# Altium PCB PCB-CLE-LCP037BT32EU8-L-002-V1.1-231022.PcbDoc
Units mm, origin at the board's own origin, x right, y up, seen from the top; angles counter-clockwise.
Board outline 48.21 x 48.21 mm, 2 copper layers (Top Layer, Bottom Layer), stack 1.571 mm thick; 83 components, 45 nets, 245 pads, 56 vias.
Unrouted connection lines stored in the file: 1.
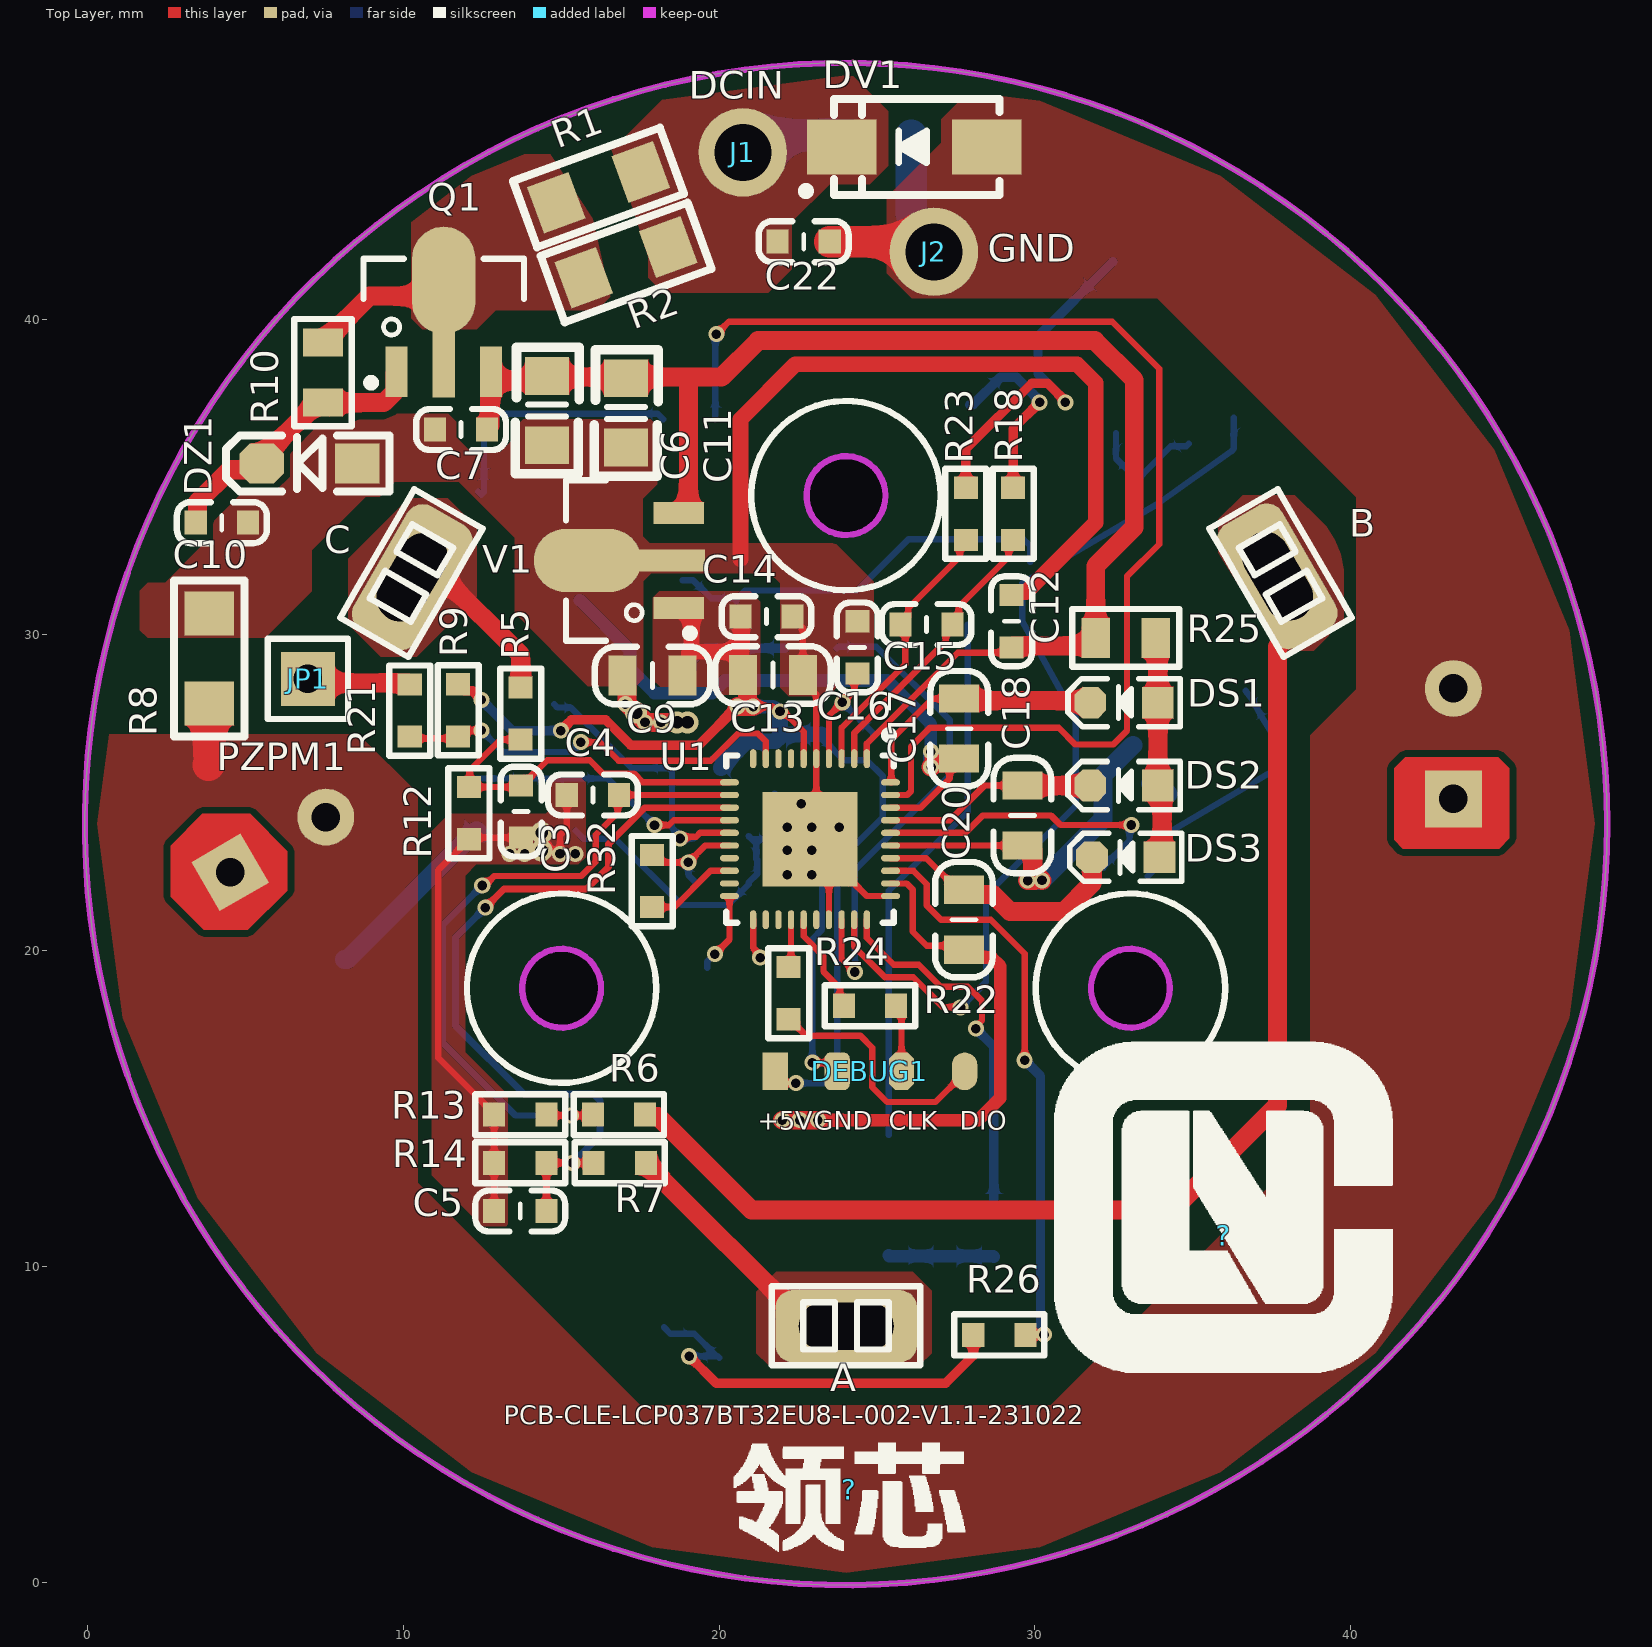
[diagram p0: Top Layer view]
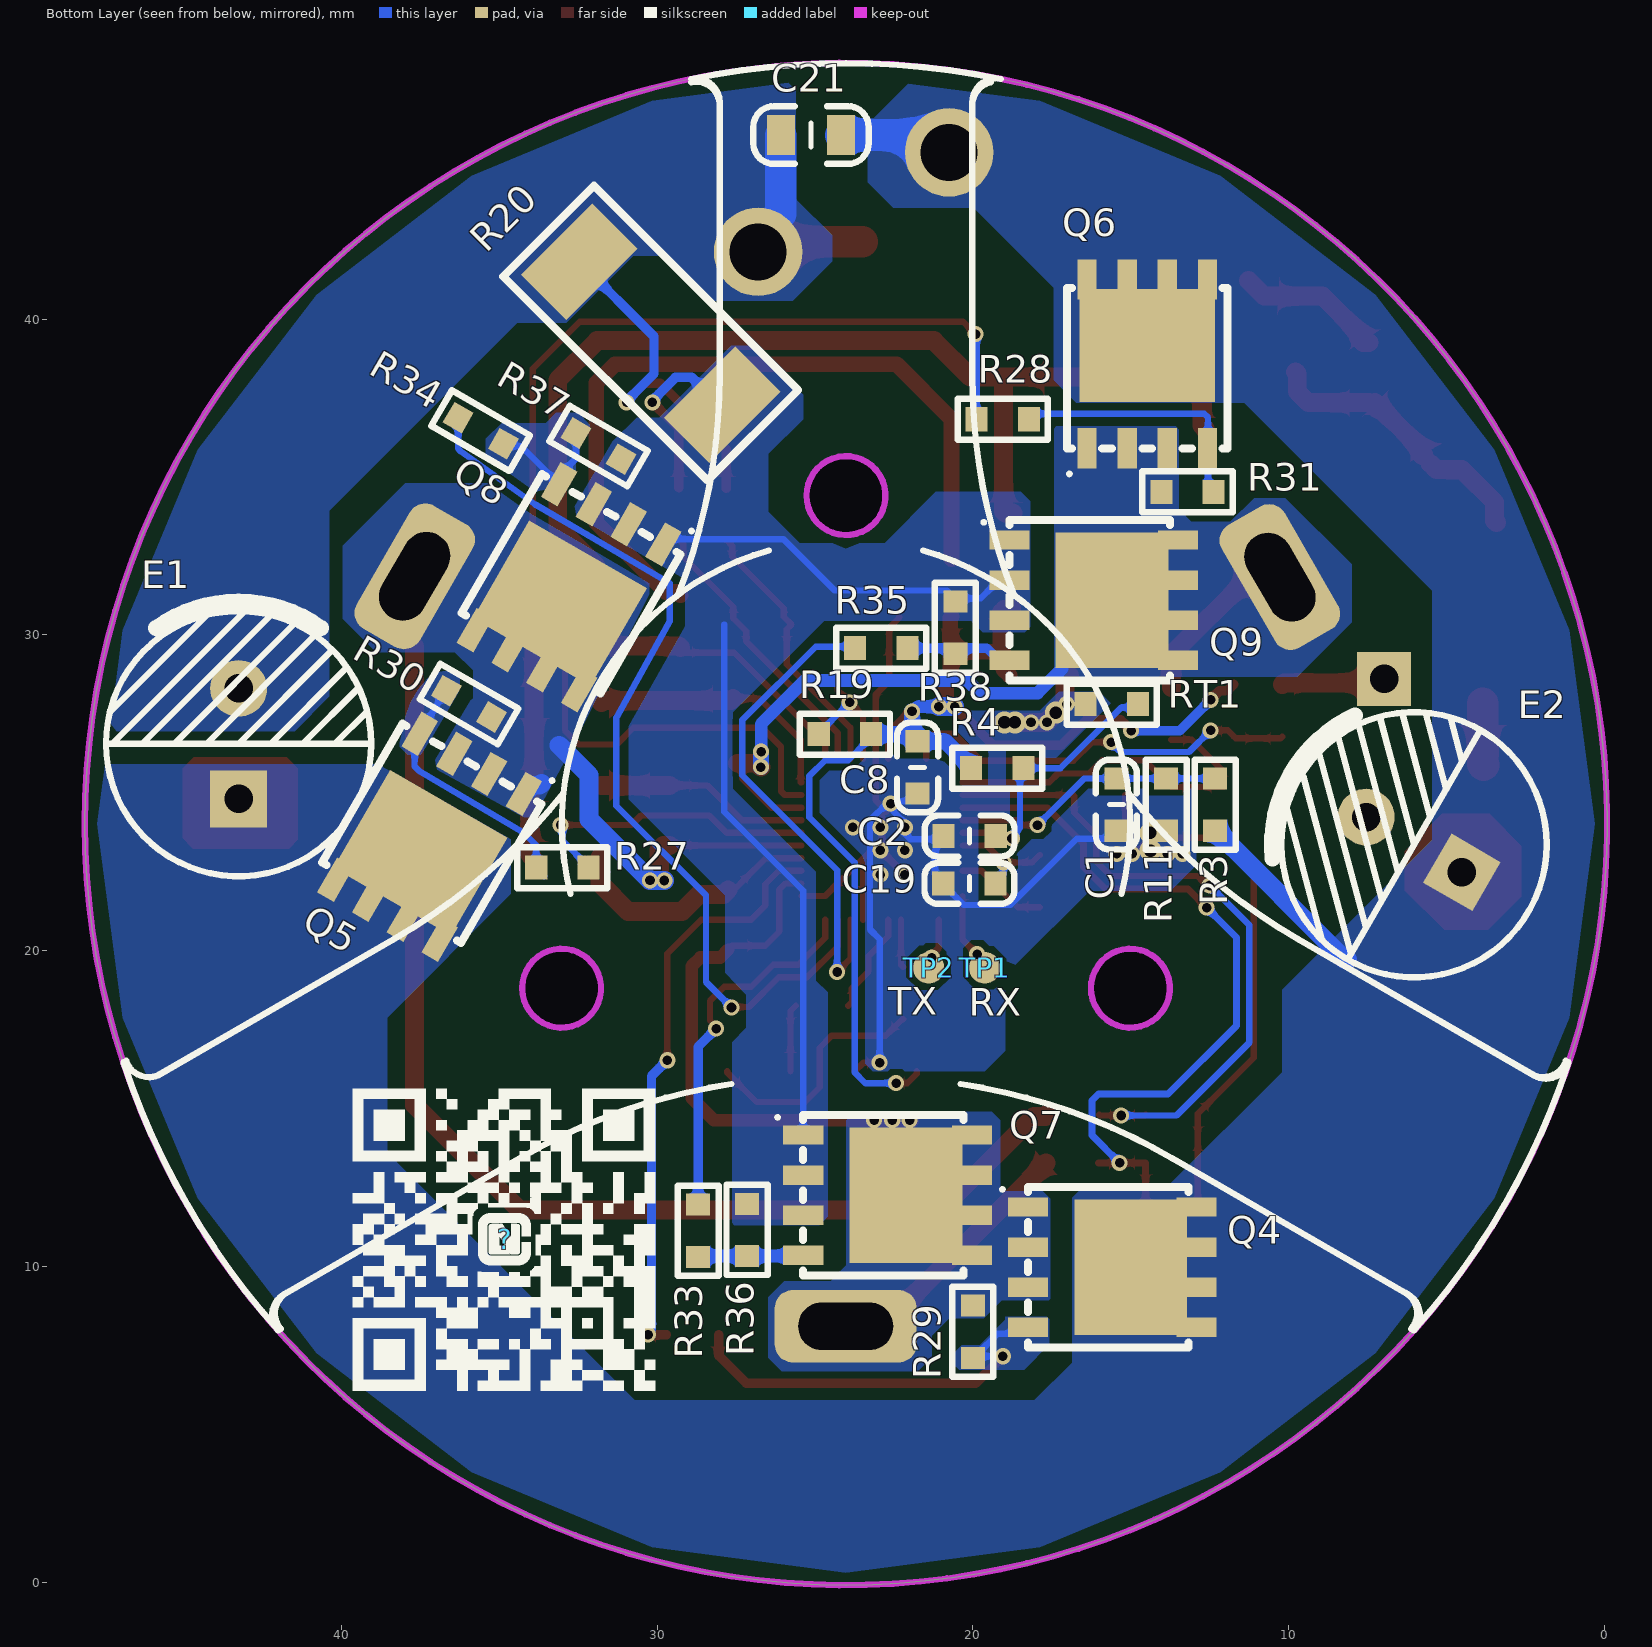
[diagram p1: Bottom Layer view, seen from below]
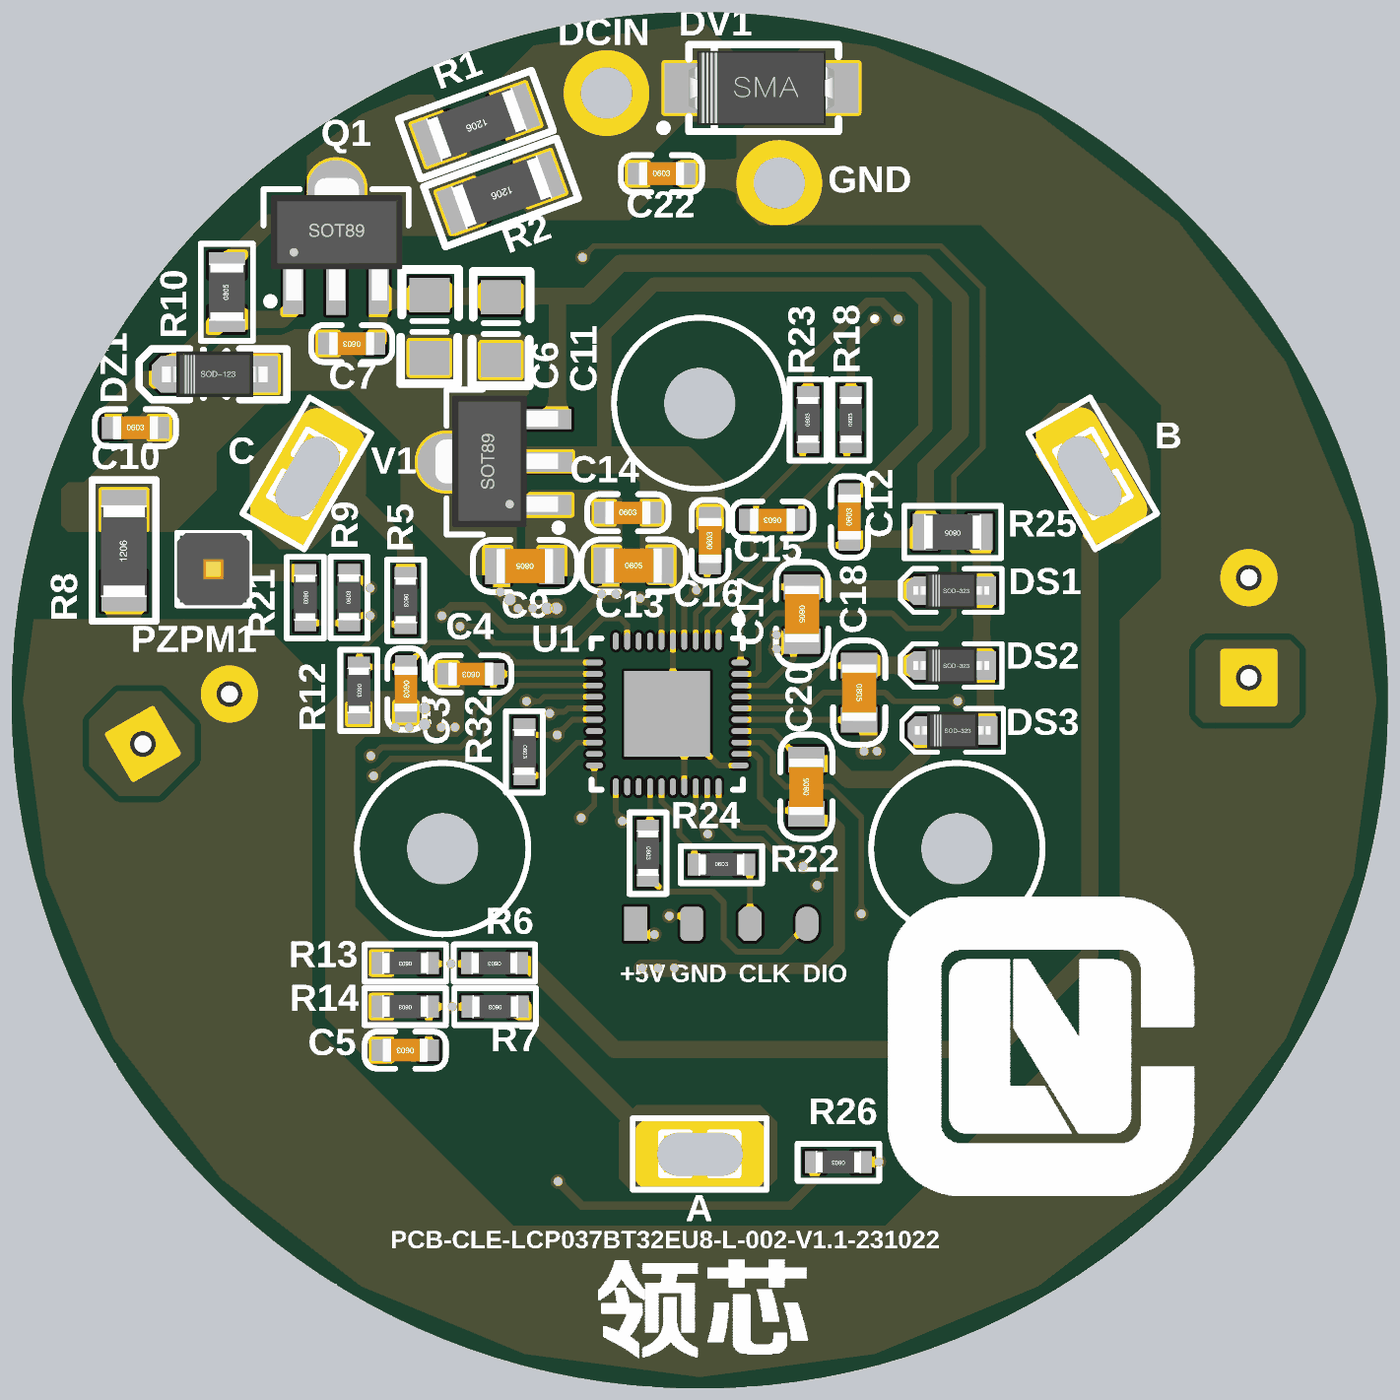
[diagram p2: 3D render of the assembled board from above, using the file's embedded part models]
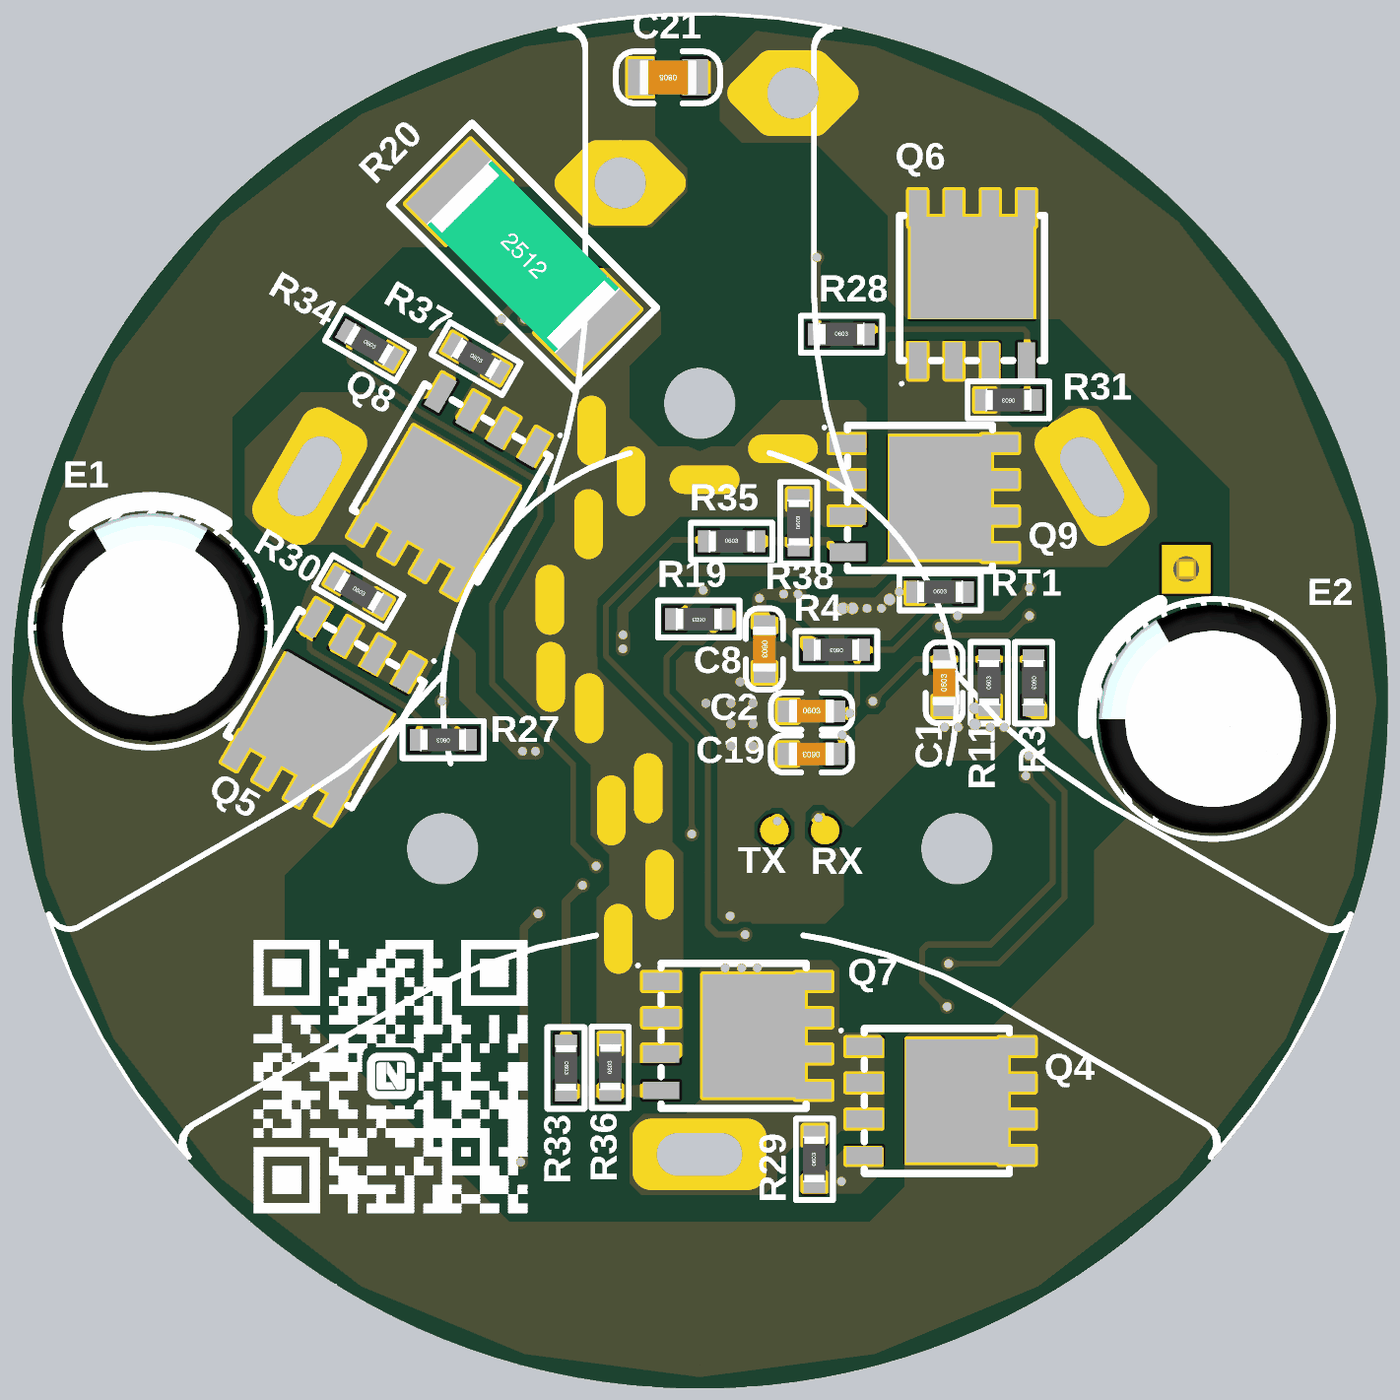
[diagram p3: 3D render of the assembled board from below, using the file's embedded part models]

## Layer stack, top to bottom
Top Solder: solder mask 0.0102, Solder Resist, Dk 3.5
Top Layer: signal copper 0.0356
Dielectric1: dielectric 1.5, FR-4, Dk 4.8
Bottom Layer: signal copper 0.0356
Bottom Solder: solder mask 0.0102, Solder Resist, Dk 3.5

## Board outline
-0.087,24.01 ccw(c24.018,24.01) 24.018,-0.095 ccw(c24.018,24.01) 48.123,24.01 ccw(c24.018,24.01) 24.018,48.114 ccw(c24.018,24.01)
cut-out: 22.768,34.41 ccw(c24.018,34.41) 24.018,33.16 ccw(c24.018,34.41) 25.268,34.41 ccw(c24.018,34.41) 24.018,35.66 ccw(c24.018,34.41)
cut-out: 13.762,18.81 ccw(c15.012,18.81) 15.012,17.56 ccw(c15.012,18.81) 16.262,18.81 ccw(c15.012,18.81) 15.012,20.06 ccw(c15.012,18.81)
cut-out: 31.775,18.81 ccw(c33.025,18.81) 33.025,17.56 ccw(c33.025,18.81) 34.275,18.81 ccw(c33.025,18.81) 33.025,20.06 ccw(c33.025,18.81)

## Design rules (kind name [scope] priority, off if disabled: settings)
Clearance [All] p1: gap=0.2 ignorepadtopadclearanceinfootprint=FALSE
ComponentClearance [All] p1: gap=0 collisioncheckmode=3 verticalgap=0 showdistances=FALSE
FabricationTestpoint [(IsPad And (OnTopLayer Or OnBottomLayer))] p1: side=3 testpointundercomponent=TRUE minsize=1.016 maxsize=2.54 preferedsize=1.524 minholesize=0 maxholesize=1.016 preferedholesize=0.813 testpointgrid=0.025 allowsidetop=TRUE allowsidebottom=TRUE usegrid=TRUE gridtolerance=0
Height [All] p1: minheight=0 maxheight=254 prefheight=12.7
HoleSize [All] p1: absolutevalues=TRUE maxlimit=25.4 minlimit=0.025 maxpercent=80.000 minpercent=20.000
HoleToHoleClearance [All] p1: gap=0 allowstackedmicrovias=TRUE
MinimumSolderMaskSliver [All] p1: minsoldermaskwidth=0
PlaneConnect [All] p1: planeconnectstyle=Direct reliefexpansion=0.508 reliefentries=4 reliefconductorwidth=0.254 reliefairgap=0.254
PolygonConnect [IsVia] p1: connectstyle=Direct reliefconductorwidth=0.254 reliefentries=4 polygonreliefangle="90 Angle" airgapwidth=0.254
PolygonConnect PolygonConnect_1 [All] p2: connectstyle=Direct reliefconductorwidth=0.254 reliefentries=4 polygonreliefangle="90 Angle" airgapwidth=0.254
RoutingVias [All] p1: holewidth=0.305 width=0.508 viastyle="Through Hole" minholewidth=0.025 minwidth=0.025 maxholewidth=0.711 maxwidth=1.27
SilkToSilkClearance [All] p1: silktosilkclearance=0
SilkToSolderMaskClearance SilkscreenOverComponentPads [IsPad] p1: minsilkscreentomaskgap=0 clearancetoexposedcopper=TRUE
SolderMaskExpansion [All] p1: expansion=0.102 istentingtop=FALSE
Width [All] p1: maxlimit=25.4 minlimit=0.025 preferedwidth=0.254
21 further rules are at their usual default settings.

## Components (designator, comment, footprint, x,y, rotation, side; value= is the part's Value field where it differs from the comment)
? "LOGO-MA" LOGO-MA 34.803,10.853 r180 bottom
? "LOGO-TU" LOGO-TU 35.977,10.972 r0 top
? "LOGO-ZI" LOGO-ZI 24.128,2.928 r0 top
C1 "104/50V" C0603 15.455,24.623 r90 bottom
C2 "103/50V" C0603 20.103,23.628 r180 bottom
C3 "102/50V" C0603 13.728,24.403 r270 top
C4 "102/50V" C0603 16.003,24.928 r180 top
C5 "102/50V" C0603 13.703,11.753 r180 top
C6 "106/50V" C0805#1 14.553,37.103 r270 top
C7 "104/50V" C0603 11.828,36.503 r180 top
C8 "104/50V" C0603 21.753,25.803 r270 bottom
C9 "106/50V" C0805#2 17.893,28.713 r180 top
C10 "104/50V" C0603 4.251,33.553 r0 top
C11 "106/50V" C0805#1 17.053,37.028 r270 top
C12 "104/50V" C0603 29.261,30.429 r90 top
C13 "106/50V" C0805#2 21.703,28.728 r0 top
C14 "104/50V" C0603 21.501,30.578 r0 top
C15 "101/50V" C0603 26.568,30.328 r180 top
C16 "104/50V" C0603 24.378,29.603 r90 top
C17 "106/25V" C0805#2 27.603,27.028 r270 top
C18 "106/25V" C0805#2 29.603,24.278 r270 top
C19 "105/50V" C0603 20.111,22.128 r0 bottom
C20 "106/25V" C0805#2 27.753,20.978 r90 top
C21 "106/50V" C0805#2 25.128,45.828 r0 bottom
C22 "104/50V" C0603 22.678,42.453 r0 top
DEBUG1 "PZ4-SHAOLU" DEBUG2.00 21.778,16.178 r0 top
DS1 "1N4148" SOD-323 32.828,27.853 r180 top
DS2 "1N4148" SOD-323 32.828,25.228 r180 top
DS3 "1N4148" SOD-323 32.878,22.953 r180 top
DV1 "SMA18V" SMA 26.178,45.453 r180 top
DZ1 "BZT52C12" SOD-123 7.028,35.428 r180 top
E1 "470uf/35V" CE-3.5-8-11 43.253,26.553 r90 bottom
E2 "470uf/35V" CE-3.5-8-11 6.028,23.353 r30 bottom
J1 "DCIN" HOLD-16AWG_RED 20.753,45.278 r180 top
J2 "GND" HOLD-16AWG_BLK 26.803,42.128 r0 top
JP1 "PZPM1" PZ2.54-D-1P 6.978,28.603 r0 top
Q1 "BCX56" SOT89 11.278,39.78 r0 top
Q4 "1511" DFN8-5*6-A 15.583,9.973 r270 bottom
Q5 "1511" DFN8-5*6-A 37.203,23.603 r30 bottom
Q6 "1511" DFN8-5*6-A 14.478,38.578 r180 bottom
Q7 "1511" DFN8-5*6-A 22.703,12.253 r270 bottom
Q8 "1511" DFN8-5*6-A 32.787,31.506 r30 bottom
Q9 "1511" DFN8-5*6-A 16.173,31.098 r270 bottom
R1 "5.1R/1206" R1206 16.203,44.178 r200 top
R2 "5.1R/1206" R1206 17.078,41.803 r200 top
R3 "100K/1%" R0603 12.328,24.623 r270 bottom
R4 "100K/1%" R0603 19.23,25.778 r0 bottom
R5 "20K/1%" R0603 13.716,27.508 r270 top
R6 "20K/1%" R0603 16.828,14.803 r180 top
R7 "20K/1%" R0603 16.853,13.278 r180 top
R8 "0R/1206" R1206 3.853,29.228 r90 top
R9 "1K" R0603 11.735,27.61 r90 top
R10 "10K" R0805 7.453,38.303 r90 top
R11 "10K/1%" R0603 13.878,24.623 r90 bottom
R12 "2.4K/1%" R0603 12.078,24.353 r270 top
R13 "2.4K/1%" R0603 13.703,14.803 r180 top
R14 "2.4K/1%" R0603 13.701,13.278 r180 top
R18 "68R/1%" R0603 29.312,33.833 r90 top
R19 "10K" R0603 24.053,26.853 r0 bottom
R20 "5mR/2512" R2512_CY 30.203,39.553 r225 bottom
R21 "1K" R0603 10.203,27.603 r270 top
R22 "100R" R0603 24.778,18.253 r0 top
R23 "68R/1%" R0603 27.813,33.833 r90 top
R24 "100R" R0603 22.203,18.653 r270 top
R25 "5.1R" R0805 32.878,29.903 r180 top
R26 "33R" R0603 28.876,7.828 r180 top
R27 "33R" R0603 33.002,22.626 r0 bottom
R28 "33R" R0603 19.053,36.828 r180 bottom
R29 "10K" R0603 20.003,7.928 r90 bottom
R30 "10K" R0603 35.962,27.815 r210 bottom
R31 "10K" R0603 13.203,34.528 r0 bottom
R32 "10K" R0603 17.878,22.203 r270 top
R33 "33R" R0603 28.703,11.128 r270 bottom
R34 "33R" R0603 35.587,36.465 r210 bottom
R35 "33R" R0603 22.903,29.578 r180 bottom
R36 "10K" R0603 27.153,11.153 r90 bottom
R37 "10K" R0603 31.853,35.978 r210 bottom
R38 "10K" R0603 20.553,30.228 r90 bottom
RT1 "10K/B=3380K" NTC-S-0603 15.601,27.803 r180 bottom
TP1 "RX" "TP 1.0" 19.628,19.455 r90 bottom
TP2 "TX" "TP 1.0" 21.403,19.453 r90 bottom
U1 "LCP037BT32EU8" LNCP-QFN40-5X5-0.4 22.878,23.528 r270 top
V1 "78L05" SOT89 17.28,32.353 r90 top

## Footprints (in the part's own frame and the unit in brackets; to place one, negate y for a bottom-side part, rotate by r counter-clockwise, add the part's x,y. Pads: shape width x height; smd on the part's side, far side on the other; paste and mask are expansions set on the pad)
C0603 [mm] "0.5/2.1"
  rect 0.7x0.762 smd: 1(-0.827,0) 2(0.827,0)
  silkscreen extent -1.42,-0.65 1.42,0.65, body extent -0.8,-0.41 0.8,0.41, height 0.84
C0805#1 [mm]
  rect 1.2x1.4 smd: 1(-1.1,0) 2(1.1,0)
  silkscreen extent -2,-1.01 2,1.02
C0805#2 [mm] "贴片MLCC电容"
  rect 0.889x1.27 smd: 1(-0.95,0) 2(0.95,0)
  silkscreen extent -1.83,-0.91 1.83,0.91, body extent -1,-0.61 1,0.61, height 0.56
CE-3.5-8-11 [mm] "直插电解电容-脚距3.5mm直径8mm高度11.5mm"
  rect 1.8x1.8 hole 0.9: 1(-1.75,0)
  round 1.8 hole 0.9: 2(1.75,0)
  silkscreen extent -4.2,-4.2 4.5,4.2, body extent -4,-4 4.01,4, height 11.64
DEBUG2.00 [mm] "烧录口2.00MM"
  rect 0.8x1.2 smd: 1(0,0)
  rrect50% 0.8x1.2 smd: 2(1.96,0)
  oct 0.8x1.2 smd: 3(4,0)
  oval 0.8x1.2 smd: 4(6,0)
DFN8-5*6-A [mm] "8-Leads, Body 6.15x5.15mm, Pitch 1.27mm;N+N"
  rect 0.61x1.27 smd: 1(-1.905,-2.67) 2(-0.635,-2.67) 3(0.635,-2.67) 4(1.905,-2.67) 5(-1.905,2.67) 5(-0.635,2.67) 5(0.635,2.67) 5(1.905,2.67)
  rect 4.3x3.574 smd: 5(0,0.581)
  silkscreen extent -2.57,-3.58 2.54,2.41
HOLD-16AWG_BLK [mm] "1.8mm"
  round 2.8 hole 1.8: 1(0,0)
  body extent -1.05,-1.05 1.05,1.05, height 36.4
HOLD-16AWG_RED [mm] "1.8mm"
  round 2.8 hole 1.8: ""(0,0)
  body extent -1.05,-1.05 1.05,1.05, height 36.4
LNCP-QFN40-5X5-0.4 [mm] "电机专用MCU-LCP037BT32EU8"
  oval 0.6x0.2 smd: 1(-2.55,1.8) 2(-2.55,1.4) 3(-2.55,1) 4(-2.55,0.6) 5(-2.55,0.2) 6(-2.55,-0.2) 7(-2.55,-0.6) 8(-2.55,-1) 9(-2.55,-1.4) 10(-2.55,-1.8) 21(2.55,-1.8) 22(2.55,-1.4) 23(2.55,-1) 24(2.55,-0.6) 25(2.55,-0.2) 26(2.55,0.2) 27(2.55,0.6) 28(2.55,1) 29(2.55,1.4) 30(2.55,1.8)
  oval 0.2x0.6 smd: 11(-1.8,-2.55) 12(-1.4,-2.55) 13(-1,-2.55) 14(-0.6,-2.55) 15(-0.2,-2.55) 16(0.2,-2.55) 17(0.6,-2.55) 18(1,-2.55) 19(1.4,-2.55) 20(1.8,-2.55) 31(1.8,2.55) 32(1.4,2.55) 33(1,2.55) 34(0.6,2.55) 35(0.2,2.55) 36(-0.2,2.55) 37(-0.6,2.55) 38(-1,2.55) 39(-1.4,2.55) 40(-1.8,2.55)
  rect 3x3 smd: 41(0,0)
  silkscreen extent -3.42,-2.65 2.65,2.65, body extent -2.5,-2.5 2.5,2.5, height 1
LOGO-MA [mm]
  silkscreen extent -4.83,-4.8 4.74,4.76
LOGO-TU [mm]
  silkscreen extent -5.36,-4.32 5.36,6.15
LOGO-ZI [mm]
  silkscreen extent -3.67,-1.95 3.67,1.48
NTC-S-0603 [mm] "0.5/2.1"
  rect 0.7x0.762 smd: 1(-0.827,0) 2(0.827,0)
  silkscreen extent -1.43,-0.65 1.43,0.65, body extent -0.8,-0.4 0.8,0.4, height 0.4
PZ2.54-D-1P [mm] "排针/直插/0.9MM孔"
  rect 1.7x1.7 hole 0.9: 1(0,0)
  silkscreen extent -1.27,-1.27 1.27,1.27, body extent -1.27,-1.27 1.27,1.27, height 8.5
R0603 [mm] "0.5/2.1"
  rect 0.7x0.762 smd: 1(-0.827,0) 2(0.827,0)
  silkscreen extent -1.43,-0.65 1.43,0.65, body extent -0.8,-0.4 0.8,0.4, height 0.4
R0805 [mil] "1/8W贴片电阻"
  rect 35x50 smd: 1(-37.4,0) 2(37.4,0)
  silkscreen extent -67,-36 67,36, body extent -39,-25 39,25, height 20
R1206 [mil] "1/4W贴片电阻"
  rect 55x62 smd: 1(-55.12,0) 2(57.09,0)
  silkscreen extent -96,-44 98,44, body extent -63,-31 63,32, height 22
R2512_CY [mm] "电流采样贴片电阻"
  rect 2.032x3.2 smd: 1(-3.2,0) 2(3.2,0)
  silkscreen extent -4.57,-2.03 4.57,2.03, body extent -3.2,-1.6 3.2,1.6, height 0.55
SMA [mm] "4.5x2.6*2.2mm"
  rect 2.2x1.75 smd: 1(-2.3,0) 2(2.3,0)
  silkscreen extent -2.7,-1.52 3.56,1.52, body extent -2.55,-1.3 2.55,1.3, height 2.15
SOD-123 [mil] "2.7x1.6X1.1mm"
  rect 55x50 smd: 1(-59.5,0)
  oct 55x50 smd: 2(59.5,0)
  silkscreen extent -100,-35 104,35, body extent -73,-32 73,31, height 50
SOD-323 [mm] "1.8x1.3X0.9mm"
  rect 1x1 smd: 1(-1.07,0)
  oct 1x1 smd: 2(1.07,0)
  silkscreen extent -1.78,-0.76 1.78,0.76, body extent -1.32,-0.65 1.32,0.65, height 0.95
SOT89 [mm] "4.6x4.3x1.6mm(长宽高)"
  rect 0.7x1.6 smd: 1(-1.5,-1.448) 3(1.5,-1.448)
  rect 0.7x2.4 smd: 2(0,-1.071)
  oval 2x3.4 smd: 2(0,1.448)
  silkscreen extent -2.54,-1.92 2.54,2.13, body extent -2.27,-1.77 2.33,2.53, height 1.6
"TP 1.0" [mm] "测试点1.0mm"
  round 1 smd paste-1.2: 1(0,0)

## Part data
C1 C2 C3 C4 C5 C7 C8 C10 C12 C14 C15 C16 C19 C22: library part CAP_0603, "贴片电容"
C6 C9 C11 C13 C17 C18 C20 C21: library part CAP_0805, "贴片电容"
DEBUG1: "烧录口"
DS1 DS2 DS3: library part DIO_SWITCHING, "开关二极管"
DV1: library part DIO_TVS_DA, "单向瞬态电压抑制二极管"
DZ1: library part DIO_ZENER, "稳压管"
E1 E2: library part CAP_CE_DIP, "直插电解电容"
J1 J2: library part CON_DY_DIP, "直插电源孔"
JP1: "排针排母"
Q1: library part D_BJT_P-3E, "NPN三极管"
Q4 Q5 Q6 Q7 Q8 Q9: library part D_MOS_N_5D, "多脚N沟道"
R1 R2 R8: library part C_RES_1206, "贴片电阻,250mW"
R3 R4 R5 R6 R7 R9 R11 R12 R13 R14 R18 R19 R21 R22 R23 R24 R26 R27 R28 R29 R30 R31 R32 R33 R34 R35 R36 R37 R38: library part C_RES_0603, "贴片电阻,100mW"
R10 R25: library part C_RES_0805, "贴片电阻,125mW"
R20: library part C_RES_CY, "贴片电流采样电阻,2W"
RT1: library part C_RES_NTC_SMD, "贴片热敏电阻"
TP1 TP2: library part TEST_DIAN, "测试点"
U1: library part MCU_合封_32位_037_B3, "037合封BT32EU8(100V-300V/40Pin/NN/QFN5*5)"
V1: library part LDO_2D/, "BUCK_DC-DC"

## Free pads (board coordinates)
  rrect50% 4.5x2.3 hole 1.5 slot 3 at 60 deg rot 60: 2(10.278,31.828)
  rrect50% 4.5x2.3 hole 1.5 slot 3 at 0 deg: 2(24.028,8.103)
  rrect50% 4.5x2.3 hole 1.5 slot 3 at 120 deg rot 120: 2(37.678,31.853)

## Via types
v1: diameter 0.508, hole 0.305, Top Layer to Bottom Layer, tented both sides, 51 vias
v2: diameter 0.7, hole 0.4, Top Layer to Bottom Layer, tented both sides, 5 vias

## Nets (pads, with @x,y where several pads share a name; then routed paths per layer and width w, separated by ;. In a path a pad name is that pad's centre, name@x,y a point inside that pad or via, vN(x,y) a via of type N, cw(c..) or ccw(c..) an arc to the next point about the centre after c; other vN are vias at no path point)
+5V: C8.1 C9.1 C13.1 C14.1 DEBUG1.1 R4.2 R9.2 R19.1 U1.6 V1.1 | length 41.6
  Top Layer w0.2: C13.1 C13.1@20.897,28.583 ; v1(21.078,27.728) 21.695,27.728 21.845,27.578 v1(21.928,27.578) 22.034,27.578 22.678,26.934 U1.6 ; DEBUG1.1 21.778,16.103 22.078,15.803 v1(22.428,15.803)
  Top Layer w0.3: R9.2 11.935,28.237 12.192,28.237 12.471,27.957 v1(12.471,27.94) ; v1(14.987,26.968) 15.324,27.305 16.408,27.305 17.203,26.51 19.36,26.51 v1(20.578,27.728)
  Top Layer w0.5: V1.1 19.028,30.853 19.128,30.753 19.128,29.603 ; C9.1 19.038,28.907 19.038,29.428 19.073,29.463 20.713,29.463 ; C14.1 20.713,30.538 20.713,29.463 ; C13.1 20.713,28.767 20.713,29.463
  Top Layer w0.6: v1(20.578,27.728) v1(21.078,27.728) 20.897,27.909 C13.1@20.897,28.583
  Bottom Layer w0.2: C8.1@21.884,26.761 C8.1@21.926,26.803 ; v1(22.428,15.803) 23.403,15.803 23.738,16.138 23.738,22.788 25.178,24.228 25.178,25.528 24.678,26.028 23.951,26.028 23.382,26.597 23.351,26.597 23.16,26.788 R19.1
  Bottom Layer w0.3: v1(12.471,27.94) 13.443,26.968 v1(14.987,26.968)
  Bottom Layer w0.4: v1(21.078,27.728) 21.749,27.728 21.899,27.578 v1(21.928,27.578)
  Bottom Layer w0.5: R4.2 20.057,25.809 20.876,26.628 C8.1@21.751,26.628 ; C8.1 21.784,26.63 C8.1@21.884,26.73 ; C8.1@21.884,26.761 C8.1@21.884,26.73 ; C8.1@21.926,26.803 21.926,27.576 v1(21.928,27.578) ; R19.1 22.007,26.853 C8.1@21.884,26.73
  Bottom Layer w0.6: v1(20.578,27.728) v1(21.078,27.728)
A: C20.1 pad.2@24.028,8.103 Q4.1 Q4.2 Q4.3 Q7.5 R7.1 R29.2 U1.32 | length 26.4
  Top Layer w0.2: U1.32 25.935,22.128 26.128,21.935 26.128,20.603 26.578,20.153 27.628,20.153 C20.1
  Top Layer w0.4: v1(23.128,14.628) 28.203,14.628 28.903,15.328 28.903,19.509 28.629,19.783 27.998,19.783 C20.1
  Top Layer w0.6: R7.1 17.68,13.274 17.682,13.272 pad.2@22.851,8.103 ; v1(22.003,14.628) v1(22.553,14.628) v1(23.128,14.628) ; pad.2@22.851,8.103 24.028,8.103 pad.2@22.851,8.103
B: C18.2 pad.2@37.678,31.853 Q5.1 Q5.2 Q5.3 Q8.5 R6.1 R30.2 U1.35 | length 52.2
  Top Layer w0.2: U1.35 C18.2
  Top Layer w0.6: R6.1 17.655,14.797 17.705,14.747 18.059,14.747 21.028,11.778 34.353,11.778 37.678,15.103 37.678,29.627 38.012,29.961 38.012,31.719 pad.2@37.778,31.953 ; C18.2 29.793,23.328 29.938,23.184 29.938,22.513 v1(30.226,22.225) ; v1(29.772,22.222) 29.776,22.225 v1@30.007,22.225
  Bottom Layer w0.6: v1(29.772,22.222) 29.776,22.225 v1(30.226,22.225) 32.153,24.152 32.153,25.553 33.103,26.503 ; 33.664,25.292 33.72,25.236 33.945,25.236 Q5.1
C: C17.2 pad.2@10.278,31.828 Q6.1 Q6.2 Q6.3 Q9.5 R5.1 R31.2 U1.38 | length 24.6
  Top Layer w0.2: U1.38 26.378,24.528 27.301,25.451 27.301,25.776 27.458,25.933 C17.2
  Top Layer w0.4: v1(26.707,26.299) 26.711,26.295 26.711,25.815 v1(26.714,25.812)
  Top Layer w0.6: pad.2@10.278,31.828 11.25,31.828 13.716,29.362 R5.1 ; v1(26.714,25.812) 26.835,25.933 C17.2@27.458,25.933
  Bottom Layer w0.4: Q9.5@15.592,31.098 17.179,29.511 17.179,28.927 17.953,28.153 19.778,28.153 20.178,28.553 25.325,28.553 26.707,27.17 v1(26.707,26.299)
  Bottom Layer w0.5: v1@26.707,25.814 v1(26.707,26.299)
DCIN: C21.1 C22.1 DV1.2 E1.1 E2.1 Q4.5 Q5.5 Q6.5 R1.1 R2.1 R3.2 | length 9.5
  Bottom Layer w0.6: 8.142,19.717 8.218,19.717 12.297,23.796 R3.2
  Bottom Layer w1: 20.753,45.278 21.24,45.278 21.79,45.828 C21.1
GAH: R26.1 U1.33 | length 18.6
  Top Layer w0.2: U1.33 26.153,22.528 26.578,22.103 26.578,21.428 27.028,20.978 28.603,20.978 29.678,19.903 v1(29.678,16.528)
  Top Layer w0.3: R26.1 29.707,7.832 30.285,7.832 v1(30.289,7.836)
  Bottom Layer w0.3: v1(29.678,16.528) 30.178,16.028 30.178,8.004 30.289,7.893 v1(30.289,7.836)
GAL: R33.1 U1.30 | length 11.8
  Top Layer w0.2: U1.30 24.678,20.403 25.528,19.553 26.318,19.553 27.018,18.853 27.878,18.853 28.328,18.403 28.328,17.799 28.128,17.599 v1(28.128,17.528)
  Bottom Layer w0.3: v1(28.128,17.528) 28.703,16.953 R33.1
GBH: R27.1 U1.36 | length 9.7
  Top Layer w0.2: U1.36 27.802,23.728 28.352,24.278 30.511,24.278 30.811,23.978 v1(33.053,23.978)
  Bottom Layer w0.2: R27.1 32.175,22.657 32.994,23.476 32.994,23.919 v1(33.053,23.978)
GBL: R34.1 U1.29 | length 29.3
  Top Layer w0.2: U1.29 24.278,20.128 25.253,19.153 26.152,19.153 27.092,18.214 27.63,18.214 v1(27.646,18.198)
  Bottom Layer w0.203: v1(27.646,18.198) 28.453,19.005 28.453,21.753 31.291,24.591 31.291,27.379 31.266,27.425 29.603,30.431 29.603,31.628 32.206,33.173 33.835,34.112 ccw(c33.684,34.374) 33.859,34.128 36.218,35.809 ccw(c36.1,35.974) 36.303,35.974 R34.1
GCH: R28.1 U1.39 | length 39
  Top Layer w0.2: v1(19.914,39.522) 20.31,39.919 32.445,39.919 33.934,38.43 33.934,32.868 32.918,31.852 32.918,26.968 32.478,26.528 31.278,26.528 30.753,27.053 26.678,27.053 26.078,26.453 26.078,25.045 25.961,24.928 U1.39
  Bottom Layer w0.2: R28.1 19.88,39.489 v1(19.914,39.522)
GCL: R35.1 U1.28 | length 15.6
  Top Layer w0.2: U1.28 23.878,19.745 v1(24.299,19.324)
  Bottom Layer w0.2: R35.1 23.78,29.628 24.978,29.628 27.303,27.303 27.303,25.553 24.299,22.549 v1(24.299,19.324)
GND: C1.1 C2.1 C3.2 C4.2 C5.2 C6.2 C7.2 C8.2 C9.2 C10.2 C11.2 C12.2 C13.2 C14.2 C16.2 C19.2 DEBUG1.2 DZ1.1 R8.2 R11.1 R12.2 R13.2 R14.2 RT1.1 U1.5 U1.27 U1.31 U1.41 V1.2 | length 82
  Top Layer w0.2: C5.2 R13.2 12.876,14.834 11.103,16.607 11.103,22.551 11.797,23.245 11.797,23.276 12.047,23.526 R12.2 12.128,23.576 C3.2 13.88,23.729 v2(14.378,23.729) 14.378,23.593 14.601,23.37 14.601,23.316 14.795,23.122 14.902,23.122 v1(14.961,23.063) 14.961,23.65 15.176,23.866 C4.2 ; C14.2 22.328,30.547 22.653,30.222 C13.2 22.653,28.537 23.078,28.112 U1.5 23.078,24.753 22.878,24.553 22.878,24.428 U1.41 U1.41@23.478,22.928 ; v1(22.953,16.453) 23.463,16.453 DEBUG1.2 ; U1.27 U1.41@23.478,22.928 ; U1.31 24.678,21.728 U1.41@23.478,22.928
  Top Layer w0.254: v1(22.153,22.403) 22.878,23.128 U1.41 ; v1(22.603,24.653) 22.603,24.578 22.753,24.428 U1.41@22.878,24.428
  Top Layer w0.5: 20.676,32.398 20.676,36.83 22.413,38.567 31.333,38.567 31.928,37.973 31.928,33.558 29.726,31.356 29.361,31.356 C12.2
  Top Layer w0.6: C9.2 17.087,28.568 17.087,27.821 v2(17.37,27.538) 17.653,27.255 v1@17.653,27.253 ; v1(17.653,27.228) v1@17.653,27.253 ; v2(18.999,27.229) v2(18.669,27.229) v1(18.161,27.229) 17.677,27.229 v1@17.653,27.253
  Bottom Layer w0.2: C1.1 15.705,23.546 16.71,23.546 18.81,21.447 20.288,21.447 20.938,22.097 C19.2 20.938,22.159 21.205,22.426 21.205,22.874 21.18,22.899 21.18,23.378 C2.1@21.03,23.528 ; C2.1 C2.1@21.03,23.528 ; C8.2 22.003,24.726 22.346,24.726 22.531,24.725 v1(22.603,24.653) ; v1(22.953,16.453) 22.953,20.363 23.26,20.67 23.26,23.903 23.26,24.124 22.731,24.653 v1(22.603,24.653) ; C2.1@21.03,23.528 21.978,23.528 22.253,23.803 22.249,23.807 22.249,24.134 22.507,24.393 22.507,24.557 v1(22.603,24.653)
  other v1: 22.928,22.403 13.36,23.063 13.843,23.063 15.443,23.063 22.153,23.178 22.928,23.178 22.153,23.903 22.928,23.903 23.803,23.903 17.028,27.803
  other v2: 14.376,23.165
IN: C6.1 C7.1 C11.1 C12.1 Q1.3 R25.2 U1.1 V1.3 | length 45.6
  Top Layer w0.2: U1.1 24.678,26.557 27.557,29.436 29.095,29.436 C12.1
  Top Layer w0.6: C7.1 12.655,36.534 12.752,36.631 12.752,38.013 Q1.3@12.793,38.053 ; Q1.3@12.778,38.053 Q1.3@12.793,38.053 ; Q1.3 12.793,38.317 Q1.3@12.793,38.053 ; C11.1 C11.1@17.016,38.165 ; V1.3 18.978,33.853 19.028,33.903 19.028,37.979 ; C12.1 29.311,29.652 31.808,29.652 31.928,29.772 31.928,32.182 33.147,33.401 33.147,38.075 31.902,39.319 21.234,39.319 20.081,38.165 19.028,38.165 C11.1@17.016,38.165 ; Q1.3@12.793,38.053 14.403,38.053 C6.1 14.591,38.165 C11.1@17.016,38.165
IR: Q7.1 Q7.2 Q7.3 Q8.1 Q8.2 Q8.3 Q9.1 Q9.2 Q9.3 R18.2 R20.2 R36.2 R37.2 R38.2 | length 35.9
  Top Layer w0.3: R18.2 29.312,36.525 v1(30.15,37.363)
  Bottom Layer w0.2: Q9.2 19.173,31.733 19.751,31.155 20.578,31.155 20.828,31.405 24.372,31.405 25.999,33.031 29.638,33.031 Q8.1 29.856,32.813 Q8.1@29.856,32.305 ; R38.2@20.515,31.093 R38.2 ; Q7.1 25.373,21.892 27.878,24.397 27.878,30.327
  Bottom Layer w0.3: R20.2 28.044,37.29 28.904,38.151 29.419,38.151 30.15,37.42 v1(30.15,37.363)
MOSTEMP: C2.2 R4.1 RT1.2 U1.15 | length 9.1
  Top Layer w0.2: v1(18.76,23.549) 18.819,23.607 19.273,23.607 19.394,23.728 U1.15
  Bottom Layer w0.2: RT1.2 14.879,27.698 15.307,27.698 17.227,25.778 R4.1 18.507,25.674 18.507,23.885 18.823,23.569 18.823,23.486 18.885,23.549 19.197,23.549 C2.2
NetC10_1: C10.1 DZ1.2 Q1.1 R10.1 | length 8.6
  Top Layer w0.6: C10.1 3.474,33.603 3.474,34.199 4.51,35.235 5.323,35.235 DZ1.2 ; DZ1.2@5.71,35.685 5.773,35.685 5.773,35.864 R10.1@7.263,37.353 ; R10.1 9.377,37.353 9.728,37.704 9.728,38.281 Q1.1
NetC17_1: C17.1 DS1.2 U1.40 | length 8.3
  Top Layer w0.2: U1.40 25.453,25.328 25.453,26.678 26.753,27.978 C17.1
  Top Layer w0.6: C17.1 27.666,27.915 31.696,27.915 DS1.2
NetC18_1: C18.1 DS2.2 U1.37 | length 6.8
  Top Layer w0.2: U1.37 27.303,24.128 28.403,25.228 C18.1
  Top Layer w0.6: C18.1 DS2.2
NetC20_2: C20.2 DS3.2 U1.34 | length 8.3
  Top Layer w0.2: U1.34 25.628,22.928 26.563,22.928 27.218,22.272 27.563,21.928 C20.2
  Top Layer w0.6: C20.2 27.898,21.783 28.667,21.783 29.216,21.234 30.914,21.234 31.809,22.129 31.809,22.952 DS3.2
NetDEBUG1_3: DEBUG1.3 R22.2 | length 2.1
  Top Layer w0.2: R22.2 25.778,18.08 DEBUG1.3
NetDEBUG1_4: DEBUG1.4 R24.2 | length 7.8
  Top Layer w0.2: R24.2 22.234,17.826 22.757,17.303 24.478,17.303 24.853,16.928 24.853,15.678 25.328,15.203 26.841,15.203 27.778,16.14 DEBUG1.4
NetDS1_1: DS1.1 DS2.1 DS3.1 R25.1 | length 7.1
  Top Layer w0.6: R25.1 33.898,29.833 DS2.1 34.032,25.094 34.032,23.037 DS3.1
NetJP1_1: JP1.1 R21.1 | length 3.3
  Top Layer w0.6: JP1.1 7.101,28.48 10.153,28.48 R21.1
NetQ1_2: Q1.2 R1.2 R2.2 R10.2 | length 4.8
  Top Layer w0.6: R10.2 7.644,39.253 7.788,39.397 7.788,39.588 8.927,40.726 10.776,40.726 Q1.2@11.278,41.228
NetQ4_4: Q4.4 R26.2 R29.1 | length 13.4
  Top Layer w0.3: v1(19.053,7.153) 19.903,6.303 27.178,6.303 28.048,7.173 R26.2 R26.2
  Bottom Layer w0.2: Q4.4 18.458,7.863 19.21,7.863 R29.1@19.92,7.153 ; v1(19.053,7.153) R29.1@19.92,7.153 ; R29.1 19.951,7.153 R29.1@19.92,7.153
NetQ5_4: Q5.4 R27.2 R30.1 | length 8.4
  Bottom Layer w0.2: R27.2@33.579,22.353 33.829,22.603 R27.2 33.829,23.339 34.188,23.697 cw(c34.329,23.556) 34.227,23.728 37.553,25.703 37.683,25.833 37.683,26.703 Q5.4 37.237,27.323 36.846,28 R30.1
NetQ6_4: Q6.4 R28.2 R31.1 | length 8.4
  Bottom Layer w0.2: R31.1 12.463,34.441 12.553,34.53 Q6.4@12.553,35.908 ; Q6.4 Q6.4@12.553,35.908 ; R28.2 18.051,37.003 12.67,37.003 12.553,36.886 Q6.4@12.553,35.908
NetQ7_4: Q7.4 R33.2 R36.1 | length 3.3
  Bottom Layer w0.4: Q7.4 25.396,10.324 28.68,10.324 R33.2
NetQ8_4: Q8.4 R34.2 R37.1 | length 4.1
  Bottom Layer w0.2: R37.1 32.569,35.586 33.102,35.054 Q8.4 34.305,35.974 34.794,35.974 R34.2
NetQ9_4: Q9.4 R35.2 R38.1 | length 3.4
  Bottom Layer w0.3: Q9.4 19.173,29.193 19.558,29.578 R35.2
NRST: C16.1 R19.2 U1.4 | length 4.5
  Top Layer w0.2: U1.4 23.478,27.44 v1(23.901,27.864) 24.281,28.243 24.281,28.679 C16.1
  Bottom Layer w0.2: v1@23.901,27.863 24.88,26.884 R19.2
OPA1_OUT: R32.2 U1.18 | length 2.9
  Top Layer w0.2: R32.2 18.576,21.376 19.728,22.528 U1.18
OPA1_OUT_LPF: C19.1 R32.1 U1.16 | length 3.4
  Top Layer w0.2: R32.1 18.115,22.793 v1(19.025,22.793) ; v1@19.092,22.86 19.56,23.328 U1.16
  Bottom Layer w0.2: v1(19.025,22.793) 19.034,22.784 19.034,22.378 C19.1
OPA1N: C15.2 R23.1 U1.3 | length 8.7
  Top Layer w0.2: U1.3 23.878,27.057 25.894,29.073 25.894,30.175 C15.2 25.991,30.578 25.991,30.843 27.622,32.473 27.622,32.815 R23.1
OPA1P: C15.1 R18.1 U1.2 | length 9
  Top Layer w0.2: U1.2 24.278,26.891 27.177,29.791 27.177,30.11 27.588,30.52 27.588,30.89 29.171,32.473 29.171,32.865 R18.1
PGND: C21.2 C22.2 DV1.1 E1.2 E2.2 J2.1 R8.1 R20.1 R23.2 | length 20.7
  Top Layer w0.3: R23.2@27.813,34.634 27.813,35.881 29.9,37.967 30.4,37.967 30.963,37.405 v1(30.963,37.363)
  Top Layer w1: 3.828,25.878 3.853,25.903 R8.1 ; C22.2 26.478,42.453 J2.1
  Bottom Layer w0.3: v1(30.963,37.363) 30.963,37.405 30.099,38.268 30.099,39.449 R20.1
  Bottom Layer w1: C21.2 26.078,43.34 26.803,42.615 J2.1
PWM_IN: R9.1 R21.2 U1.9 | length 13.1
  Top Layer w0.2: R21.2 10.258,26.721 11.673,26.721 R9.1 11.927,26.975 v1(12.471,26.975) ; v1(15.622,26.6) 16.224,26.6 16.815,26.009 19.735,26.009 20.599,26.873 21.233,26.873 21.478,26.628 U1.9
  Bottom Layer w0.2: v1(12.471,26.975) 13.157,26.289 15.311,26.289 v1(15.622,26.6)
RXD: TP1.1 U1.20 | length 2.6
  Top Layer w0.2: v1(19.863,19.888) 20.328,20.353 U1.20
  Bottom Layer w0.2: TP1.1 19.628,19.653 v1(19.863,19.888)
SWCLK: R22.1 U1.25 | length 3.3
  Top Layer w0.2: U1.25 22.678,20.453 23.303,19.828 23.303,19.338 23.824,18.817 23.824,18.38 R22.1
SWDIO: R24.1 U1.24 | length 1.5
  Top Layer w0.2: R24.1 22.278,19.555 U1.24
TXD: TP2.1 U1.21 | length 1.3
  Top Layer w0.2: U1.21 21.078,20.086 21.303,19.861 v1(21.303,19.778)
VMA: C5.1 R7.2 R14.1 U1.13 | length 24.5
  Top Layer w0.2: 17.653,24.518 17.663,24.528 U1.13
  Top Layer w0.22: v1(12.595,21.361) 13.186,21.953 15.803,21.953 16.503,22.653 16.503,23.378 17.643,24.518 17.653,24.518 ; C5.1 14.53,13.276 R14.1 R7.2
  Bottom Layer w0.22: v1(12.595,21.361) 11.653,20.42 11.653,17.62 13.819,15.453 16.028,15.453 16.228,15.253 16.228,14.153 v1(15.353,13.278)
VMB: C4.1 R6.2 R13.1 U1.12 | length 21.8
  Top Layer w0.2: v1(12.499,22.063) 12.582,22.063 12.882,22.363 15.633,22.363 16.093,22.823 16.093,23.668 16.789,24.364 16.789,24.887 C4.1 U1.12 ; v1(15.303,14.778) 15.976,14.778 R6.2
  Top Layer w0.203: R13.1 14.555,14.778 v1(15.303,14.778)
  Bottom Layer w0.203: v1(12.499,22.063) 11.241,20.806 11.241,17.09 13.553,14.778 v1(15.303,14.778)
VMC: C3.1 R5.2 R12.1 U1.11 | length 11.4
  Top Layer w0.2: 15.899,26.028 16.318,25.609 17.304,25.609 17.585,25.328 U1.11
  Top Layer w0.203: R12.1 12.101,25.203 12.101,25.716 13.067,26.681 R5.2 ; R12.1@12.153,25.18 13.678,25.18 C3.1 13.759,25.23 14.557,26.028 15.899,26.028
VOLDECT: C1.2 R3.1 R11.2 U1.14 | length 8.7
  Top Layer w0.2: v1(17.953,23.974) 18.405,23.974 18.559,24.128 U1.14
  Bottom Layer w0.2: R3.1 R11.2 16.477,25.45 v1(17.953,23.974)
pads on no net: J1. U1.7 U1.8 U1.10 U1.17 U1.19 U1.22 U1.23 U1.26

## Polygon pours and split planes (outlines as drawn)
NetQ5_4 on Bottom Layer "NETQ5_4_L02_P021" (solid, remove dead copper, pour order 21): 36.928,28.853 36.383,28.853 36.253,28.723 36.253,28.503 36.278,28.203 37.128,26.778 37.478,26.203 37.903,26.203 38.153,26.453 38.153,26.603 38.001,27.147 ccw(c35.538,26.835) 37.059,28.797 37.028,28.828
NetQ4_4 on Bottom Layer "NETQ4_4_L02_P017" (solid, remove dead copper, pour order 17): 17.653,8.403 17.578,8.328 17.578,7.528 18.378,6.728 20.428,6.728 20.553,6.853 20.553,7.303 20.353,7.503 19.778,7.503 18.978,8.303 18.978,8.403
NetQ8_4 on Bottom Layer "NETQ8_4_L02_P013" (solid, remove dead copper, pour order 13): 33.203,37.028 32.503,37.028 32.128,36.653 32.128,36.503 32.569,36.062 32.569,35.187 33.378,34.378 33.963,34.378 34.987,35.402 35.077,35.402 35.428,35.753 35.428,36.203 34.928,36.703 33.528,36.703
PGND on Bottom Layer "PGND_L02_P012" (solid, remove dead copper, pour order 12): 25.603,46.453 25.603,43.803 24.453,42.653 24.453,41.828 25.703,40.578 28.503,40.578 29.928,42.003 30.753,42.003 32.878,39.878 34.428,39.878 40.378,33.928 40.378,28.053 41.478,26.953 47.778,26.953 48.453,27.628 48.453,33.678 34.328,47.803 26.078,47.803 25.603,47.328
GND on Bottom Layer "GND_L02_P010" (solid, remove dead copper, pour order 10): 17.878,27.603 20.753,27.603 21.478,28.328 24.453,28.328 25.478,27.303 25.478,24.203 23.478,22.203 23.478,16.478 23.178,16.178 19.628,16.178 18.974,16.832 18.974,19.232 16.303,21.903 13.735,21.903 12.928,22.71 12.928,25.18 12.989,25.18 14.987,27.178 16.003,28.194 17.287,28.194
IR on Bottom Layer "IR_L02_P007" (solid, remove dead copper, pour order 7): 27.893,21.788 27.848,21.743 27.848,19.298 27.178,18.603 27.178,17.553 27.628,17.103 27.628,11.378 27.553,11.303 24.678,11.303 24.603,11.378 24.603,18.678 24.978,19.053 24.978,22.503 27.603,25.128 27.603,27.553 26.478,28.678 24.714,30.442 20.051,30.442 19.688,30.078 18.353,30.078 18.178,30.253 18.178,34.228 18.478,34.528 21.172,34.528 22.797,32.903 25.478,32.903 26.478,33.903 26.478,35.728 25.378,36.828 25.378,37.602 26.929,39.153 27.653,39.153 29.928,36.878 30.653,36.878 31.403,36.128 32.628,34.028 32.628,33.753 32.603,33.728 29.103,31.758 29.103,30.277 30.903,27.112 30.903,24.797
DCIN on Bottom Layer "DCIN_L02_P003" (solid, remove dead copper, pour order 3): 23.328,46.178 21.228,48.278 13.178,48.278 -0.747,34.353 -0.747,13.328 13.028,-0.447 34.853,-0.447 48.778,13.478 48.778,24.878 47.753,25.903 38.853,25.903 34.628,23.519 34.628,21.803 38.553,17.878 38.553,13.603 30.703,5.753 18.053,5.753 16.853,6.953 16.853,12.178 16.528,12.503 13.853,12.503 10.203,16.153 10.203,18.753 5.453,23.503 5.453,31.403 11.403,37.353 16.728,37.353 17.437,38.062 17.437,40.987 19.978,43.528 22.528,43.528 23.328,44.328
A on Bottom Layer "A_L02_P002" (solid, remove dead copper, pour order 2): 18.455,12.372 17.703,12.378 17.553,12.228 17.553,8.978 17.603,8.928 19.078,8.928 19.653,8.353 20.753,8.353 21.303,7.803 21.303,7.128 21.753,6.678 26.053,6.678 26.478,7.103 26.478,9.028 25.978,9.528 24.503,9.528 24.003,10.028 24.003,14.628 23.728,14.903 19.403,14.903 19.128,14.628 19.128,12.503 19.003,12.378
B on Bottom Layer "B_L02_P001" (solid, remove dead copper, pour order 1): 34.653,34.803 33.378,33.528 30.428,31.903 30.253,31.728 30.253,31.278 32.703,26.428 33.772,24.466 34.01,24.228 34.228,24.228 37.003,25.753 37.053,25.803 37.053,26.003 35.898,27.925 35.828,27.995 35.828,28.878 36.403,29.453 38.903,29.453 39.953,30.503 39.953,32.828 37.978,34.803
C on Bottom Layer "C_L02_P000" (solid, remove dead copper, pour order 0): 16.203,36.603 13.578,36.603 13.478,36.503 13.478,33.978 13.078,33.578 11.843,33.578 11.093,34.328 10.103,34.328 8.003,32.228 8.003,30.403 9.728,28.678 17.278,28.678 17.428,28.828 17.428,36.528 17.353,36.603
A on Top Layer "A_L01_P020" (solid, remove dead copper, pour order 20): 25.335,9.828 21.803,9.828 21.178,9.203 21.178,7.253 21.565,6.866 26.341,6.866 26.728,7.253 26.728,9.228 26.128,9.828
B on Top Layer "B_L01_P019" (solid, remove dead copper, pour order 19): 38.228,34.428 36.578,34.428 35.803,33.653 35.803,32.603 37.682,29.63 37.809,29.503 38.828,29.503 39.79,30.465 39.79,31.814 ccw(c37.25,31.814) 39.046,33.61
C on Top Layer "C_L01_P018" (solid, remove dead copper, pour order 18): 11.103,34.328 10.178,34.328 8.253,32.403 8.253,30.328 9.278,29.303 10.428,29.303 12.328,31.203 12.328,33.403 11.403,34.328
NetQ1_2 on Top Layer "NETQ1_2_L01_P015" (solid, remove dead copper, pour order 15): 14.653,45.228 12.253,45.228 10.253,43.228 10.253,40.028 10.603,39.678 12.328,39.678 12.928,40.278 16.128,40.278 16.553,40.703 16.003,43.178
DCIN on Top Layer "DCIN_L01_P014" (solid, remove dead copper, pour order 14): 19.678,48.428 16.603,45.353 17.278,43.478 17.753,41.953 17.753,41.303 18.228,40.828 21.553,40.828 22.303,41.578 22.303,43.078 23.503,44.278 24.778,44.278 25.353,44.853 25.353,46.578 23.503,48.428
GND on Top Layer "GND_L01_P011" (solid, remove dead copper, pour order 11): 15.678,25.428 15.528,25.578 14.896,25.578 14.603,25.285 14.603,24.422 14.511,24.33 11.455,24.33 10.903,23.778 10.903,12.878 12.503,11.278 13.253,11.278 13.303,11.328 13.303,15.428 11.953,16.778 11.953,22.376 12.305,22.728 15.745,22.728 15.778,22.761 15.778,25.328
+5V on Top Layer "+5V_L01_P009" (solid, remove dead copper, pour order 9): 18.103,31.378 17.903,31.178 17.903,28.578 18.128,28.353 19.678,28.353 19.928,28.103 21.253,28.103 21.303,28.153 21.303,31.053 20.978,31.378
GND on Top Layer "GND_L01_P008" (solid, remove dead copper, pour order 8): 1.653,31.403 1.653,30.153 1.903,29.903 5.628,29.903 7.103,31.378 7.103,32.678 8.803,34.378 9.253,34.378 9.728,34.853 11.753,34.853 13.528,33.078 13.528,30.693 15.843,28.378 17.368,28.378 17.603,28.613 17.603,31.703 17.853,31.953 21.603,31.953 21.928,31.628 21.928,28.328 22.203,28.053 24.526,28.055 24.892,28.421 24.892,31.674 23.663,32.903 22.797,32.903 17.803,32.903 17.578,33.128 17.578,34.303 18.043,34.768 18.043,36.613 17.828,36.828 13.803,36.828 13.528,36.553 13.528,36.253 13.078,35.803 12.128,35.803 11.678,36.253 11.678,36.753 11.428,37.003 7.403,37.003 3.701,33.301 3.701,32.9 2.454,31.653 1.903,31.653
PGND on Top Layer "PGND_L01_P005" (solid, remove dead copper, pour order 5): 40.178,29.656 40.178,28.278 38.728,26.828 38.728,13.828 30.503,5.603 17.503,5.603 10.453,12.653 10.453,24.978 8.578,26.853 0.653,26.853 -1.072,25.128 -1.072,13.828 13.278,-0.522 35.578,-0.522 48.228,12.128 48.228,28.678 45.289,31.617
PGND on Top Layer "PGND_L01_P004" (solid, remove dead copper, pour order 4): 25.303,41.453 26.103,40.653 33.878,40.653 40.178,34.353 40.178,28.778 41.603,27.353 46.253,27.353 48.103,29.203 48.103,35.928 36.953,47.078 27.778,47.078 27.028,46.328 27.028,45.578 25.303,43.853

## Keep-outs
Keep-Out Layer:
  circle w0.2: c24.018,34.41 r1.25
  circle w0.2: c33.025,18.81 r1.25
  circle w0.2: c15.012,18.81 r1.25
  circle w0.2: c24.018,24.01 r24.105

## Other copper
Top Layer:
  region net DCIN: 43.678,26.128 41.728,26.128 41.378,25.778 41.378,23.503 41.653,23.228 44.703,23.228 45.028,23.553 45.028,25.778 44.678,26.128
  region net DCIN: 4.903,24.328 3.628,24.328 2.628,23.328 2.628,21.703 3.678,20.653 5.078,20.653 6.328,21.903 6.328,23.153 5.153,24.328

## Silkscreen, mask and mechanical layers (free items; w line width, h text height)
Top Overlay:
  circle w0.2: c33.025,18.81 r3
  circle w0.2: c24.018,34.41 r3
  circle w0.2: c15.012,18.81 r3
  lines w0.2: 7.997,30.546 10.162,29.296 10.662,30.162 11.162,31.028 11.512,31.634 12.012,32.5 12.512,33.366 10.347,34.616 9.847,33.75 9.347,32.884 8.997,32.278 8.497,31.412 7.997,30.546 ; 8.93,31.162 9.43,32.028 10.729,31.278 10.229,30.412 8.93,31.162 ; 9.78,32.634 10.28,33.5 11.579,32.75 11.079,31.884 9.78,32.634 ; 21.668,6.866 21.668,9.366 22.668,9.366 23.668,9.366 24.368,9.366 25.368,9.366 26.368,9.366 26.368,6.866 25.368,6.866 24.368,6.866 23.668,6.866 22.668,6.866 21.668,6.866 ; 22.668,7.366 23.668,7.366 23.668,8.866 22.668,8.866 22.668,7.366 ; 24.368,7.366 25.368,7.366 25.368,8.866 24.368,8.866 24.368,7.366 ; 35.524,33.366 36.024,32.5 36.524,31.634 36.874,31.028 37.374,30.162 37.874,29.296 40.04,30.546 39.54,31.412 39.04,32.278 38.69,32.884 38.19,33.75 37.69,34.616 35.524,33.366 ; 36.457,32.75 37.756,33.5 38.256,32.634 36.957,31.884 36.457,32.75 ; 37.307,31.278 38.606,32.028 39.106,31.162 37.807,30.412 37.307,31.278
  text "B" at 39.953,32.828 h1.5
  text "C" at 7.493,32.3 h1.5
  text "+5V" at 21.228,14.14 h1
  text "GND" at 23.003,14.14 h1
  text "CLK" at 25.378,14.139 h1
  text "DIO" at 27.628,14.14 h1
  text "A" at 23.52,5.766 h1.5
  text "PCB-CLE-LCP037BT32EU8-L-002-V1.1-231022" at 13.178,4.815 h1
Bottom Overlay:
  lines w0.2: 1.22,16.509 ccw(c1.937,16.745) 1.23,16.481 ccw(c1.93,16.742) 1.289,16.359 1.293,16.352 ccw(c1.933,16.743) 1.517,16.119 1.518,16.118 ccw(c1.933,16.743) 1.827,16.001 ccw(c1.933,16.748) 1.855,15.997 ccw(c1.933,16.741) 1.99,15.996 1.993,15.996 ccw(c1.933,16.743) 2.308,16.094 ; 6.124,8.016 cw(c6.683,8.516) 5.963,8.304 5.963,8.307 cw(c6.68,8.516) 5.937,8.44 cw(c6.688,8.516) 5.934,8.468 cw(c6.683,8.516) 5.986,8.794 5.987,8.795 cw(c6.683,8.516) 6.169,9.063 6.175,9.068 cw(c6.681,8.518) 6.283,9.15 cw(c6.685,8.512) 6.308,9.166 ; 15.071,24.987 cw(c0.149,36.886) 9.692,20.357 2.223,16.045 cw(c1.845,16.699) 2.197,16.031 cw(c1.849,16.692) 2.072,15.979 2.065,15.976 cw(c1.848,16.694) 1.742,15.952 1.74,15.952 cw(c1.848,16.694) 1.432,16.07 cw(c1.85,16.698) 1.409,16.086 cw(c1.846,16.692) 1.307,16.175 1.305,16.177 cw(c1.848,16.694) 1.136,16.459 ccw(c24.018,24.01) 6.038,7.968 cw(c6.602,8.47) 6.019,7.99 cw(c6.596,8.465) 5.943,8.102 5.939,8.109 cw(c6.598,8.467) 5.849,8.42 5.849,8.421 cw(c6.598,8.467) 5.902,8.747 cw(c6.602,8.465) 5.913,8.773 cw(c6.596,8.468) 5.979,8.891 5.981,8.893 cw(c6.598,8.467) 6.223,9.117 13.692,13.429 cw(c23.235,-3.1) 20.391,15.773 ; 15.295,21.796 cw(c24.018,24.01) 21.573,32.671 ; 18.698,31.269 ccw(c0.932,38.243) 20.018,38.243 20.018,46.867 ccw(c19.268,46.867) 19.471,47.589 ccw(c19.267,46.862) 19.446,47.596 ccw(c19.268,46.867) 19.287,47.617 ; 19.116,47.601 cw(c24.018,24.01) 28.921,47.601 ; 19.431,47.501 cw(c19.268,46.77) 19.446,47.498 19.447,47.497 cw(c19.269,46.772) 19.575,47.453 cw(c19.266,46.765) 19.6,47.442 cw(c19.268,46.769) 19.857,47.233 19.858,47.232 cw(c19.268,46.769) 19.998,46.941 20,46.933 cw(c19.271,46.769) 20.018,46.799 cw(c19.263,46.769) 20.018,46.769 ; 26.463,32.671 cw(c24.018,24.01) 32.742,21.796 ; 27.645,15.773 cw(c24.802,-3.1) 34.345,13.429 41.813,9.117 cw(c41.436,8.463) 41.839,9.101 cw(c41.44,8.469) 41.946,9.019 41.952,9.014 cw(c41.438,8.467) 42.135,8.746 42.135,8.745 cw(c41.439,8.467) 42.187,8.42 cw(c41.433,8.467) 42.185,8.393 cw(c41.438,8.467) 41.998,7.968 ccw(c24.018,24.01) 46.901,16.459 cw(c46.184,16.696) 46.891,16.431 cw(c46.191,16.693) 46.832,16.31 46.828,16.303 cw(c46.189,16.694) 46.731,16.176 cw(c46.185,16.698) 46.712,16.157 ; 28.018,46.769 cw(c28.768,46.769) 28.091,47.091 28.092,47.093 cw(c28.766,46.771) 28.161,47.209 cw(c28.772,46.766) 28.178,47.232 cw(c28.768,46.769) 28.434,47.441 28.435,47.441 cw(c28.768,46.769) 28.75,47.519 28.758,47.519 cw(c28.768,46.772) 28.892,47.509 cw(c28.767,46.764) 28.921,47.503 ; 28.46,47.551 ccw(c28.77,46.863) 28.434,47.539 ccw(c28.768,46.867) 28.038,47.038 28.036,47.031 ccw(c28.766,46.867) 28.019,46.897 ccw(c28.773,46.867) 28.018,46.867 28.018,38.243 ccw(c47.104,38.243) 29.338,31.269 ; 32.965,24.987 ccw(c47.888,36.886) 38.345,20.357 45.813,16.045 ; 41.729,9.166 cw(c41.354,8.516) 42.039,8.821 cw(c41.349,8.514) 42.05,8.795 cw(c41.354,8.516) 42.102,8.47 42.102,8.468 cw(c41.354,8.516) 42.012,8.157 42.008,8.15 cw(c41.356,8.515) 41.932,8.039 cw(c41.35,8.519) 41.913,8.016 ; 45.879,16.028 45.887,16.025 ccw(c46.104,16.743) 46.044,15.996 ccw(c46.104,16.749) 46.071,15.994 ccw(c46.104,16.743) 46.646,16.225 ccw(c46.104,16.743) 46.656,16.236 ccw(c46.104,16.743) 46.816,16.509
Bottom Solder:
  lines w1: 20.377,32.814 21.827,32.814 ; 23.127,31.739 24.577,31.739 ; 25.417,16.827 25.417,18.277 ; 25.817,20.202 25.817,21.652 ; 26.419,30.957 26.419,32.407 ; 26.867,14.927 26.867,16.377 ; 27.117,19.427 27.117,20.877 ; 27.803,32.728 27.803,34.178 ; 27.892,23.002 27.892,24.452 ; 27.914,29.453 27.914,30.903 ; 29.242,24.102 29.242,25.552 ; 29.267,26.802 29.267,28.252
